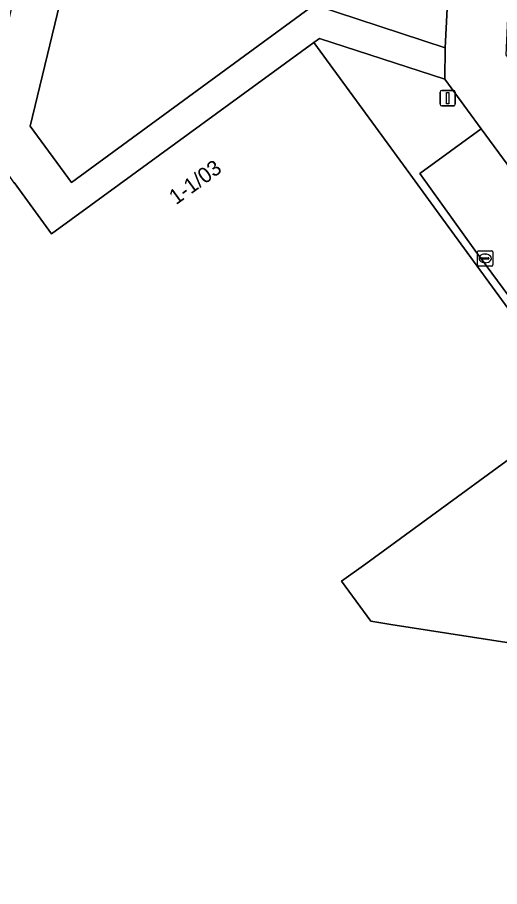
# Model space of a CAD drawing. Extents: x 161090 to 161692, y 379509 to 380907.
# Drawn here: x 161274.3 to 161305.8, y 380819.4 to 380876.1 of the extents above; entities that cross this region are included whole.
import ezdxf

# ---------------------------------------------------------------- set-up
doc = ezdxf.new("R2010")
doc.units = 0
for name, color, linetype in [('IMGEO_Groenvoorziening', 7, 'Continuous'), ('IMGEO_Kolk', 7, 'Continuous'), ('IMGEO_Lichtmast', 7, 'Continuous'), ('IMGEO_Pand', 7, 'Continuous'), ('IMGEO_Pand_nummerreeks', 7, 'Continuous'), ('IMGEO_Parkeervlak_open', 7, 'Continuous'), ('IMGEO_Rijbaan_lokaal_open', 7, 'Continuous'), ('IMGEO_Voetpad_open', 7, 'Continuous')]:
    doc.layers.add(name, color=color, linetype=linetype)

msp = doc.modelspace()

# ---------------------------------------------------------------- linework, layer by layer
at = {"layer": 'IMGEO_Groenvoorziening'}
for points in [[(161293.658, 380876.966), (161302.206, 380874.169), (161302.568, 380881.457), (161279.123, 380885.638), (161275.111, 380869.035), (161277.805, 380865.373)], [(161303.657, 380870.085), (161302.186, 380872.114), (161293.999, 380874.768), (161293.631, 380874.499), (161297.65, 380868.996), (161300.061, 380865.693), (161301.815, 380863.291), (161311.016, 380850.691), (161311.468, 380851.012), (161304.146, 380860.954), (161300.557, 380865.96), (161304.557, 380868.865)]]:
    msp.add_lwpolyline(points, close=True, dxfattribs=at)
at = {"layer": 'IMGEO_Kolk'}
for p, q in [((161304.313, 380859.983), (161304.313, 380860.835)), ((161304.388, 380860.909), (161305.24, 380860.909)), ((161305.314, 380860.835), (161305.314, 380859.983)), ((161304.572, 380860.403), (161304.572, 380860.415)), ((161305.01, 380860.366), (161304.612, 380860.366)), ((161304.615, 380860.452), (161305.013, 380860.452)), ((161304.801, 380860.689), (161304.826, 380860.689)), ((161305.056, 380860.415), (161305.056, 380860.403)), ((161305.24, 380859.909), (161304.388, 380859.909)), ((161304.824, 380860.129), (161304.799, 380860.129))]:
    msp.add_line(p, q, dxfattribs=at)
for points in [[(161304.313, 380859.983), (161304.313, 380860.835)], [(161304.388, 380860.909), (161305.24, 380860.909)], [(161305.314, 380860.835), (161305.314, 380859.983)], [(161305.24, 380859.909), (161304.388, 380859.909)]]:
    msp.add_lwpolyline(points, dxfattribs=at)
for centre, radius, start, end in [((161304.39, 380860.833), 0.0765, 91.552, 178.448), ((161304.39, 380860.833), 0.0765, 91.552, 178.448), ((161305.238, 380860.833), 0.0765, 1.552, 88.448), ((161305.238, 380860.833), 0.0765, 1.552, 88.448), ((161304.612, 380860.412), 0.0403, 85.8775, 175.7526), ((161304.609, 380860.402), 0.0366, 178.938, 274.7102), ((161305.013, 380860.409), 0.043, 264.8664, 352.4533), ((161305.017, 380860.414), 0.0386, 1.7309, 96.639), ((161304.39, 380859.985), 0.0765, 181.552, 268.448), ((161304.39, 380859.985), 0.0765, 181.552, 268.448), ((161305.238, 380859.985), 0.0765, 271.552, 358.448), ((161305.238, 380859.985), 0.0765, 271.552, 358.448)]:
    msp.add_arc(centre, radius, start, end, dxfattribs=at)
for centre, major_axis, ratio, start_param, end_param in [((161304.8, 380860.409), (-0.387, 0.002), 0.722429, 4.712389, 7.853982), ((161304.825, 380860.409), (-0.39, 0.002), 0.717154, 1.570796, 4.712389)]:
    msp.add_ellipse(centre, major_axis=major_axis, ratio=ratio, start_param=start_param, end_param=end_param, dxfattribs=at)
at = {"layer": 'IMGEO_Lichtmast'}
for p, q in [((161301.872, 380870.475), (161301.872, 380871.275)), ((161301.872, 380871.275), (161301.872, 380870.475)), ((161301.972, 380871.375), (161302.762, 380871.375)), ((161302.762, 380871.375), (161301.972, 380871.375)), ((161302.862, 380871.275), (161302.862, 380870.475)), ((161302.862, 380870.475), (161302.862, 380871.275)), ((161302.762, 380870.375), (161301.972, 380870.375)), ((161301.972, 380870.375), (161302.762, 380870.375))]:
    msp.add_line(p, q, dxfattribs=at)
msp.add_lwpolyline([(161302.292, 380871.25), (161302.442, 380871.25), (161302.442, 380870.5), (161302.292, 380870.5), (161302.292, 380871.25)], dxfattribs=at)
for centre, start, end in [((161301.972, 380871.275), 90, 180), ((161301.972, 380871.275), 90, 180), ((161302.762, 380871.275), 0, 90), ((161302.762, 380871.275), 360, 90), ((161301.972, 380870.475), 180, 270), ((161301.972, 380870.475), 180, 270), ((161302.762, 380870.475), 270, 0), ((161302.762, 380870.475), 270, 0)]:
    msp.add_arc(centre, 0.1, start, end, dxfattribs=at)
at = {"layer": 'IMGEO_Pand'}
msp.add_lwpolyline([(161336.848, 380819.378), (161334.032, 380819.813), (161327.677, 380820.795), (161327.827, 380821.683), (161334.36, 380826.485), (161335.14, 380832.159), (161335.444, 380834.369), (161330.618, 380840.979), (161328.148, 380841.364), (161322.714, 380842.211), (161316.181, 380837.441), (161315.622, 380833.857), (161298.659, 380836.502), (161297.352, 380836.706), (161295.443, 380839.321), (161297.016, 380840.47), (161311.016, 380850.691), (161301.815, 380863.291), (161300.061, 380865.693), (161297.65, 380868.996), (161293.631, 380874.499), (161279.082, 380863.878), (161276.517, 380862.005), (161274.07, 380865.356)], dxfattribs=at)
at = {"layer": 'IMGEO_Parkeervlak_open'}
msp.add_lwpolyline([(161304.557, 380868.865), (161300.557, 380865.96), (161304.146, 380860.954), (161311.468, 380851.012), (161314.33, 380847.126), (161318.367, 380850.08)], close=True, dxfattribs=at)
at = {"layer": 'IMGEO_Rijbaan_lokaal_open'}
msp.add_lwpolyline([(161311.914, 380870.415), (161309.729, 380868.769), (161306.191, 380873.695), (161306.292, 380876.085), (161306.491, 380880.768), (161302.568, 380881.457), (161302.206, 380874.169), (161302.186, 380872.114), (161303.657, 380870.085), (161304.557, 380868.865), (161318.367, 380850.08), (161322.471, 380853.084), (161323.99, 380854.186)], close=True, dxfattribs=at)
at = {"layer": 'IMGEO_Voetpad_open'}
for points in [[(161255.03, 380853.506), (161273.043, 380866.778), (161274.053, 380865.344), (161274.07, 380865.356), (161276.517, 380862.005), (161279.082, 380863.878), (161293.631, 380874.499), (161293.999, 380874.768), (161302.186, 380872.114), (161302.206, 380874.169), (161293.658, 380876.966), (161277.805, 380865.373), (161275.111, 380869.035), (161279.123, 380885.638), (161276.152, 380886.159), (161271.851, 380868.388), (161272.446, 380867.595), (161254.232, 380854.161), (161250.213, 380843.988), (161250.895, 380843.069)], [(161311.468, 380851.012), (161311.016, 380850.691), (161297.016, 380840.47), (161295.443, 380839.321), (161297.352, 380836.706), (161298.659, 380836.502), (161315.622, 380833.857), (161316.181, 380837.441), (161322.714, 380842.211), (161328.148, 380841.364), (161330.618, 380840.979), (161327.742, 380844.918), (161331.183, 380844.292), (161327.526, 380849.234), (161323.99, 380854.186), (161322.471, 380853.084), (161325.497, 380848.94), (161321.349, 380845.873), (161321.754, 380845.364), (161317.594, 380842.294), (161314.157, 380846.988), (161314.33, 380847.126)]]:
    msp.add_lwpolyline(points, close=True, dxfattribs=at)

# ---------------------------------------------------------------- texts
at = {"layer": 'IMGEO_Pand_nummerreeks'}
msp.add_text('1-1/03', height=1, rotation=36.1307, dxfattribs=at).set_placement((161284.639, 380863.874))

doc.saveas('drawing.dxf')
